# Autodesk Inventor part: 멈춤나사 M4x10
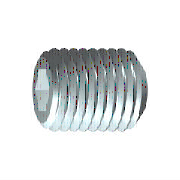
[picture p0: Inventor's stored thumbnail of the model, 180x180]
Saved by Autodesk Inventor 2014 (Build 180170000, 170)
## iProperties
Created: 2012-02
Part Number: 멈춤나사 M4x10
Material: 강철, 연강
Description: 6각 소켓 머리 없는 멈춤 나사
Document SubType Name: Modeling
Standard: KS B 1028
Designer: mduedu
Standards Organization: KS
Language: ko-KR
Size Designation: 납작점M4x10
Categories: <MemberInstance><Categories><Category DisplayName="조임쇠" InternalName="e4da775c-781d-43d5-af7c-5136215cf5a6" Mnemonic="FSTN"><Category DisplayName="볼트" InternalN
Density: 1 g/cm^3
Appearance: Steel
IsCustomPart: 1
Author: mduedu
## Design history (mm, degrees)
sketch "스케치1"
  geometry: L1 (0, 0)-(6.833, 0); L2 (10, 1.155)-(10, 2); L3 (10, 2)-(0, 2); L4 (10, 1.155)-(7.5, 1.155); L5 (7.5, 1.155)-(6.833, 0); L6 (0, -0.4)-(0, 2.4) reference; L7 (0, 2)-(0, 0)
  constraints: 13 end point, 3 parallel, 1 collinear, 1 perpendicular, 1 point on line
  dimensions: "d0" = 2.5 distance of L2.start L4.end (= INTI); "d1" = 60 deg angle of L5 L1; "d2" = 4 diameter of L3 L1 (= NND); "d3" = 2.3094 diameter of L4 L1 (= 1.1547 x SW); "d5" = 10 distance from line of L2 L3.end (= NLG)
revolve "본체" sketch "스케치1" stored, may be unused: angle "d6" = 90 deg
sketch "스케치2"
  geometry: L1 (-0.577, 1)-(0.577, 1); L2 (0.577, 1)-(1.155, 0); L3 (1.155, 0)-(0.577, -1); L4 (0.577, -1)-(-0.577, -1); L5 (-0.577, -1)-(-1.155, 0); L6 (-1.155, 0)-(-0.577, 1); A1 r 1.155 centre (0, 0) between (-0.577, 1) and (0.577, 1) reference; 2 further points
  constraints: 12 end point, 2 point on circle, 1 coincident, 1 horizontal, 11 other
extrude "슬롯" join sketch "스케치2" taper "d9" = 0 deg; stored distance "d21" = 10
workaxis "Work Axis1"
workplane "Work Plane1"
body "Solid1"
chamfer "모따기1" distance "d7" = 0.42941 (= -0.5 x GD1 + 0.5 x NND); stored, may be unused: angle "d8" = 45 deg (= FAWI), second distance "d29" = 0.42941 (= -0.5 x GD1 + 0.5 x NND)
feature "스레드" dims "d11" = 10 (= NLG), "d12" = 0
chamfer "모따기2" distance "d13" = 0.42941 (= -0.5 x GD1 + 0.5 x NND); stored, may be unused: angle "d14" = 45 deg (= FAWI), second distance "d30" = 0.42941 (= -0.5 x GD1 + 0.5 x NND)
other parameters: "NND" = 4 [user parameter; used in 5 equation terms], "NLG" = 10 [user parameter; used in 2 equation terms], "INTI" = 2.5 [user parameter; used in 1 equation term], "FAWI" = 45 deg [user parameter; used in 2 equation terms], "SW" = 2 [user parameter; used in 2 equation terms], "GD1" = 3.14117 (= THREADDIA - 1.2269 x PTC) [user parameter; used in 4 equation terms], "d4" = 0, "FAWI1" = 45 deg [user parameter], "d15" = 0, "d31" = 0, "GUL" = 0.42941 (= 0.61345 x PTC) [user parameter], "SPD" = 2.5 [user parameter], "TPU" = 14.28571 (computed from PTC) [user parameter], "TOA" = 30 deg [user parameter], "THREADDIA" = 4 [user parameter; used in 1 equation term], "PTC" = 0.7 [user parameter; used in 4 equation terms], "GAL" = 0.42941 (= 0.61345 x PTC) [user parameter], "E0" = 2.31 (= 1.155 x SW) [user parameter]
